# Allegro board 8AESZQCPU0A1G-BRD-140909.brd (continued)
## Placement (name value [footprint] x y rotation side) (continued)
R314  *10K 1% 1/16W  [R0402]  120.37 23.34 90 bottom
R315  0ohm 5% 1/4W  [R1206]  47.5 23.22 90 bottom
R316  487 1% 1/10W  [R0603]  51.56 22.35 0 bottom
R317  100ohm 1% 1/16W  [R0402]  134.6 22.33 0 bottom
R318  1K 1% 1/16W  [R0402]  92.96 21.67 270 bottom
R319  *100ohm 1% 1/16W  [R0402]  134.6 21.32 180 bottom
R320  10K 1% 1/16W  [R0402]  52.32 20.95 0 bottom
R321  4.12K 1%  [R0402]  119.38 19.94 0 bottom
R322  1K 1% 1/16W  [R0402]  99.39 19.89 90 bottom
R323  2.87K 1% 1/16W  [R0402]  117.83 18.21 270 bottom
R324  301K 1% 1/16W  [R0402]  69.19 18.13 90 bottom
R325  22.1K 1% 1/16W  [R0402]  67.92 18.13 90 bottom
R326  2.2 ohm 5% 1/16W  [R0402]  98.96 17.76 180 bottom
R327  ***0ohm 5% 1/16W  [R0402]  75.16 17.48 180 bottom
R328  2.2 ohm 5% 1/16W  [R0402]  90.4 17.23 0 bottom
R329  2.2 ohm 5% 1/16W  [R0402]  98.96 16.67 180 bottom
R330  2.2 ohm 5% 1/16W  [R0402]  90.4 16.21 0 bottom
R331  9.76K 1% 1/16W  [R0402]  69.16 15.95 0 bottom
R332  100K 1% 1/16W  [R0402]  73.66 15.88 0 bottom
R333  2.87K 1% 1/16W  [R0402]  122.22 15.57 270 bottom
R334  3.57K 1% 1/16W  [R0402]  121.11 15.57 270 bottom
R335  301K 1% 1/16W  [R0402]  70.74 15.49 90 bottom
R336  10K 1% 1/16W  [R0402]  52.53 13.54 90 bottom
R337  10K 1% 1/16W  [R0402]  125.48 13.21 90 bottom
R338  10K 1% 1/16W  [R0402]  54.18 12.95 270 bottom
R339  121K 1% 1/16W  [R0402]  47.68 12.5 180 bottom
R340  510 5% 1/16W  [R0402]  58.24 12.22 270 bottom
R341  1K 1% 1/16W  [R0402]  122.28 11.79 180 bottom
R342  10K 1% 1/16W  [R0402]  109.22 11.18 0 bottom
R343  10K 1% 1/16W  [R0402]  122.17 10.41 180 bottom
R344  22.1K 1% 1/16W  [R0402]  47.68 10.31 180 bottom
R345  1K 1% 1/16W  [R0402]  58.24 10.24 270 bottom
R346  1K 1% 1/16W  [R0402]  112.85 10.21 0 bottom
R347  7.68K 1% 1/16W  [R0402]  114.38 8.97 90 bottom
R348  150 1% 1/16W  [R0402]  112.8 8.97 0 bottom
R349  7.68K 1% 1/16W  [R0402]  111.35 8.84 270 bottom
R350  10K 1% 1/16W  [R0402]  93.85 8.76 90 bottom
R351  10K 1% 1/16W  [R0402]  92.58 8.76 90 bottom
R352  6.65K 1% 1/10W  [R0603]  112.55 6.98 90 bottom
R353  20 1% 1/16W  [R0402]  114.15 6.09 90 bottom
R354  *10K 1% 1/16W  [R0402]  109.45 5.1 0 bottom
R355  6.65K 1% 1/10W  [R0603]  113.01 4.39 180 bottom
R356  10K 1% 1/16W  [R0402]  109.45 4.08 0 bottom
R751  ***0ohm 5% 1/16W  [R0402]  66.42 9.14 270 bottom
R752  ***0ohm 5% 1/16W  [R0402]  65.02 9.14 270 bottom
S1  PCIEX16_GOLDFINGER  [PCI_E_X16_A]  98.4 3.5 180 bottom
TP1  TP  [T30]  91.47 63.63 0 top
TP2  TP  [T30]  92.1 62.51 0 top
TP3  TP  [T30]  105.92 52.66 0 top
TP4  TP  [T30]  10.31 40.94 270 top
TP5  TP  [T30]  101.57 37.97 0 top
TP6  TP  [T30]  110.96 35.72 0 top
TP7  TP  [T30]  122.44 56.5 270 bottom
TP8  TP  [T30]  46.25 53.9 180 bottom
TP9  TP  [T30]  124.33 51.54 270 bottom
TP10  TP  [T30]  130.81 40.23 270 bottom
TP11  TP  [T30]  98.17 37.08 180 bottom
TP12  TP  [T30]  120.14 36.96 180 bottom
TP13  TP  [T30]  99.57 36.7 180 bottom
TP14  TP  [T30]  115.87 35.66 180 bottom
TP15  TP  [T30]  122.84 33.69 180 bottom
TP16  TP  [T30]  122.16 30.89 180 bottom
TP17  TP  [T30]  121.34 27.3 180 bottom
TP18  TP  [T30]  124.46 24.33 180 bottom
TP19  TP  [T30]  121.51 24.13 180 bottom
TP20  TP  [T30]  125.53 23.62 180 bottom
TP47  TP  [T30]  43.36 52.28 180 bottom
TP48  TP  [T30]  42.73 61.17 180 bottom
TP49  TP  [T30]  24.36 54.02 180 bottom
TP51  TP  [T30]  41.41 55.16 180 bottom
TP52  TP  [T30]  40.92 63.09 180 bottom
U1  SN74LVC1G07DBVR  [SOT_25]  45.7 70.3 0 top
U2  IR3553MTRPBF  [LCC25_4X6_0P5]  101.06 68.31 90 top
U3  IR3570AMTRPBF  [LCC40_5X5_0P4]  85.81 66.6 270 top
U4  SECOS BAT54C  [SOT_23]  14.73 60.07 180 top
U5  G751-2P1f  [SOP8_1P27_6]  19.43 59.69 0 top
U6  74AVC1T45  [SOT_363]  49.76 57.53 0 top
U7  MAX V 5M1270ZF256  [BGA256_16X16_1P0]  37.32 57.12 90 top
U8  PCA9511ADP  [SOP8_0P65_4P9]  24.26 51.82 0 top
U9  AT24C128C-SSHM-T  [SOP8_1P27_6]  19.43 51.69 0 top
U10  74AVC1T45  [SOT_363]  102.49 50.79 0 top
U11  SN74LVC1G07DBVR  [SOT_25]  39.35 43.91 0 top
U12  IR3553MTRPBF  [LCC25_4X6_0P5]  65.18 42.9 90 top
U13  SN74LVC1G07DBVR  [SOT_25]  39.4 39.29 180 top
U14  AVOTON_EXT_BGA  [BGA1283A]  129.97 39.05 0 top
U15  N25Q128A13ESE40 NEW  [SOP8_1P27_7P9]  28.93 38.59 180 top
U16  W25Q64FVSSIG  [SOP8_1P27_7P9]  34.77 38.59 180 top
U17  HPA01110DQPR  [LCC22_5X6_0P5_JNPR_1]  15.24 38.05 0 top
U18  IRFHS8242TRPBF  [LCC6_2X2_0P65_D]  70.51 34.92 270 top
U19  IRFHS8242TRPBF  [LCC6_2X2_0P65_D]  70.51 32.64 270 top
U20  IR3537MTRPBF  [LCC10_3X3_0P5]  65.94 32.46 270 top
U21  6V61036NDG  [LCC40_5X5_0P4]  98.12 32.16 180 top
U22  BAT54C  [SOT_23]  34.92 32.11 90 top
U23  IR3570AMTRPBF  [LCC40_5X5_0P4]  53.52 31.33 90 top
U24  CAT25256YI-GT3  [SOP8_0P65_6P4]  105.87 28.85 0 top
U25  TPS54225PWPR  [SOP14_0P65_6P4_EP_JNPR_1]  70.59 23.69 0 top
U26  TPS74701DRC  [LCC10_3X3_0P5]  121.18 19 90 top
U27  6U49420D  [LCC48_6X6_0P4]  95.86 18.6 270 top
U28  TPS74701DRC  [LCC10_3X3_0P5]  80.17 17.57 180 top
U29  TPS54225PWPR  [SOP14_0P65_6P4_EP]  50.42 16.36 0 top
U30  TPS74701DRC  [LCC10_3X3_0P5]  121.78 13.35 0 top
U31  IR3899MTRPBF  [LCC17_4X5_0P5]  113.8 8.35 270 top
U32  ISL90728  [SOT_363]  142.82 4.11 180 top
U33  LM321MF/NOPB  [SOT_25]  148.72 3.43 270 top
U34  ISL90727WIE627Z-T7A  [SOT_363]  161.16 3.43 180 top
U35  LM321MF/NOPB  [SOT_25]  167 3.43 270 top
U36  SN74LVC1G07DBVR  [SOT_25]  132.61 68.12 180 bottom
U37  SN74LVC1G07DBVR  [SOT_25]  137.41 67.82 180 bottom
U38  TPS51200DRCR  [LCC10_3X3_0P5]  126.69 66.95 270 bottom
U39  N-CH AP2302GN-HF  [SOT_23]  71.73 18.46 270 bottom
U40  N-CH AP2302GN-HF  [SOT_23]  72.69 13.13 270 bottom
U41  FET N-CH IRLML2402  [SOT_23]  51.46 10.9 270 bottom
U42  FET N-CH IRLML2402  [SOT_23]  55.7 10.64 270 bottom
X1  25MHz 3.3V  [OSC4_SCO_A571]  50.57 63.93 180 top
X2  32.768KHZ  [XTAL2_TXC_9H]  108.48 38.89 90 top
X3  14.31818MHz  [XTAL4_FL2000006]  89.45 23.49 90 top

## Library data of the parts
A1 = SCREW HOLE_3: Tolerance: ***; User Part Number: ***
B1 B3 = 2B: Tolerance: ***; User Part Number: ***
B2 = 2B: User Part Number: ***; Tolerance: ***
C1-C5 C7-C12 C14 C15 C17-C21 C23 C24 C26-C28 C30 C38 C39 C42 C45-C47 C49-C51 C53-C58 C60-C92 C94-C102 C108 C110 C113 C116-C145 C147-C155 C157 C158 C162-C164 C166-C177 C179-C183 C185-C195 C197-C231 C233 C234 C236-C239 C241 C244-C249 C251 C252 C255-C258 C260 C261 C263 C265-C291 C293 C295-C326 C328-C355 C357-C363 C365-C373 C375-C377 C379-C413 C415-C420 C422-C424 C426 C427 C432-C438 C440 C441 C443-C445 C449 C452-C456 C458-C485 C489-C496 C500 C501 = CAP_NP: Tolerance: ***; User Part Number: ***
C6 C16 C25 C48 C52 C59 C93 C107 C111 C146 C156 C159 C160 C165 C178 C184 C232 C262 C292 C294 C356 C364 C374 C378 C414 C439 C446 C451 C457 C486-C488 C497-C499 = CAP_NP: User Part Number: ***; Tolerance: ***
C13 C327 C442 = CAP_NP: Tolerance: ***; User Part Number: ***; room: PHY
C22 C43 C44 C105 C161 C259 = CAP: Tolerance: ***; User Part Number: ***
C29 C31-C35 C37 C40 C41 C235 C240 C242 C243 C253 C254 C428-C431 = CAP_NP: Tolerance: ***; User Part Number: ***; signal model: CAP_NP_C0402_0.1UF_16V_0.1uF_16V
C36 = CAP_NP: Tolerance: ***; User Part Number: ***; signal model: CAP_NP_C0402_0.1UF_16V
C103 C421 C450 = CAP NP: Tolerance: ***; User Part Number: ***; room: REG_1_2V1
C104 C106 C109 C112 = CAP_NP: Tolerance: ***; User Part Number: ***; signal model: CAP_NP_C0402_10NF_50V_10NF_50V
C114 C115 C196 = CAP: User Part Number: ***; Tolerance: ***
C250 C264 C425 R1-R7 R9-R14 R18 R20-R25 R27 R28 R30-R58 R60-R86 R88-R109 R111-R208 R210-R213 R215-R239 R241 R243-R245 R247-R341 R343-R346 R350 R351 R751 R752 = R: Tolerance: ***; User Part Number: ***
D1-D10 = LED: Tolerance: ***; User Part Number: ***
D11 = DIODE_ZENER_0: Tolerance: ***; User Part Number: ***
J1-J5 = JP3_0603: Tolerance: ***; User Part Number: ***
JP1 = JP3: User Part Number: ***; Tolerance: ***
JP2 = JP5A: User Part Number: ***; Tolerance: ***
JP3 JP5 = JTAG_2x5: User Part Number: ***; Tolerance: ***
JP4 = Heatsink_Hole: Tolerance: ***; User Part Number: ***
L1 L2 L4-L6 L8-L10 L14 L17-L21 = INDUCTOR: Tolerance: ***; User Part Number: ***
L3 L7 L11-L13 L15 L16 = INDUCTOR: User Part Number: ***; Tolerance: ***
N1 N3 N5-N9 N12 N14 N18-N20 N27 N28 N31-N34 N37 N38 N40-N42 N51 N56-N58 N60 = R_0OHM: Tolerance: ***; User Part Number: ***
N2 N4 N10 N11 N13 N15-N17 N21-N26 N29 N30 N35 N36 N39 N43-N50 N52-N55 N59 = R_0OHM: User Part Number: ***; Tolerance: ***
P1 = DDR3 ECC SO-DIMM 204PIN: Tolerance: ***; User Part Number: ***; room: DDR3
P2 = CON60,ITP-XDP_0: User Part Number: C21100-002; Tolerance: ***
P3 = SATA CONN_1: Tolerance: ***; User Part Number: ***
P4 = DDR3 ECC SO-DIMM 204PIN: User Part Number: ***; Tolerance: ***; room: DDR3
Q1 Q2 = RT9164_1: Tolerance: ***; User Part Number: ***
R8 R16 R19 R242 R246 R342 R347-R349 R352-R356 = R: User Part Number: ***; Tolerance: ***
R15 R17 R59 R110 R240 = RT: Tolerance: ***; User Part Number: ***
R26 R29 R209 R214 = R: Tolerance: ***; User Part Number: ***; signal model: CAP_NP_C0402_0.1UF_16V_0.1uF_16V
R87 = R: Tolerance: ***; User Part Number: ***; room: MPC8245
S1 = 2134415-2_3: User Part Number: ***; Tolerance: ***
TP1-TP6 TP8 TP11-TP20 TP47-TP49 TP51 TP52 = JP1_0: Tolerance: ***; User Part Number: ***; room: DDR_DIV
TP7 TP9 TP10 = JP1_0: User Part Number: ***; Tolerance: ***; room: DDR_DIV
U1 U11 U13 U36 U37 = SN74LVC1G07DBVR_0: Tolerance: ***; User Part Number: ***
U2 U12 = IR3553MTRPBF: Tolerance: ***; User Part Number: ***
U3 U23 = IR3570AMTRPBF: User Part Number: ***; Tolerance: ***
U4 U22 = RB425DT146: Tolerance: ***; User Part Number: ***
U5 = G751: User Part Number: ***; Tolerance: ***
U6 U10 = 74AVC1T45GW_1: Tolerance: ***; User Part Number: ***
U7 = MAXV5M1270ZF256: Tolerance: ***; User Part Number: ***
U8 = PCA9511ADP: Tolerance: ***; User Part Number: ***
U9 = 24LC08B: User Part Number: ***; Tolerance: ***
U14 = AVOTON_EXT_BGA_0: Tolerance: ***; User Part Number: ***
U15 U16 = W25Q64FVSSIG_0: Tolerance: ***; User Part Number: ***
U17 = TPS53353_1: Tolerance: ***; User Part Number: ***
U18 U19 = IRFHS8242TR2PBF_4: User Part Number: ***; Tolerance: ***
U20 = IR3537MTRPBF: Tolerance: ***; User Part Number: ***
U21 = 6V61036NDG: Tolerance: ***; User Part Number: ***
U24 = 25LC256: Tolerance: ***; User Part Number: ***
U25 U29 = TPS54226_1: Tolerance: ***; User Part Number: ***
U26 U30 = TPS74701DRC: Tolerance: ***; User Part Number: ***
U27 = 6P49420NDG: User Part Number: ***; Tolerance: ***
U28 = TPS74701DRC: User Part Number: ***; Tolerance: ***
U31 = IR3899MTRPBF: User Part Number: ***; Tolerance: ***
U32 = ISL90728: Tolerance: ***; User Part Number: ***
U33 U35 = LM321MF/NOPB: Tolerance: ***; User Part Number: ***
U34 = ISL90728WIE627Z_0: Tolerance: ***; User Part Number: ***
U38 = TPS51200DRCR: Tolerance: ***; User Part Number: ***
U39-U42 = ZVN3310F: Tolerance: ***; User Part Number: ***
X1 = OSC_SMD: User Part Number: ***; Tolerance: ***
X2 = XTAL_0: Tolerance: ***; User Part Number: ***
X3 = XTAL4_3: Tolerance: ***; User Part Number: ***

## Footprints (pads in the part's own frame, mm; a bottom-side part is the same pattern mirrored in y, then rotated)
0_OHM_2PIN
  custom 0.127x0.127 smd: 1(-0.318,0) 2(0.318,0)
2B
  round 1.016 smd: 1(0,0) 2(0,0)
A126_DG_3
  round 3.2 hole 3.2 unplated: (0,0)
  round 1.194 hole 0.381: 3(-1.732,1.732) 4(-1.732,-1.732) 6(0,2.451) 7(0,-2.451) 8(-2.451,0)
BGA256_16X16_1P0
  round 0.457 smd: A1(-7.5,-7.5) A2(-7.5,-6.5) A3(-7.5,-5.5) A4(-7.5,-4.5) A5(-7.5,-3.5) A6(-7.5,-2.5) A7(-7.5,-1.5) A8(-7.5,-0.5) A9(-7.5,0.5) A10(-7.5,1.5) A11(-7.5,2.5) A12(-7.5,3.5) A13(-7.5,4.5) A14(-7.5,5.5) A15(-7.5,6.5) A16(-7.5,7.5) B1(-6.5,-7.5) B2(-6.5,-6.5) B3(-6.5,-5.5) B4(-6.5,-4.5) B5(-6.5,-3.5) B6(-6.5,-2.5) B7(-6.5,-1.5) B8(-6.5,-0.5) B9(-6.5,0.5) B10(-6.5,1.5) B11(-6.5,2.5) B12(-6.5,3.5) B13(-6.5,4.5) B14(-6.5,5.5) B15(-6.5,6.5) B16(-6.5,7.5) C1(-5.5,-7.5) C2(-5.5,-6.5) C3(-5.5,-5.5) C4(-5.5,-4.5) C5(-5.5,-3.5) C6(-5.5,-2.5) C7(-5.5,-1.5) C8(-5.5,-0.5) C9(-5.5,0.5) C10(-5.5,1.5) C11(-5.5,2.5) C12(-5.5,3.5) C13(-5.5,4.5) C14(-5.5,5.5) C15(-5.5,6.5) C16(-5.5,7.5) D1(-4.5,-7.5) D2(-4.5,-6.5) D3(-4.5,-5.5) D4(-4.5,-4.5) D5(-4.5,-3.5) D6(-4.5,-2.5) D7(-4.5,-1.5) D8(-4.5,-0.5) D9(-4.5,0.5) D10(-4.5,1.5) D11(-4.5,2.5) D12(-4.5,3.5) D13(-4.5,4.5) D14(-4.5,5.5) D15(-4.5,6.5) D16(-4.5,7.5) E1(-3.5,-7.5) E2(-3.5,-6.5) E3(-3.5,-5.5) E4(-3.5,-4.5) E5(-3.5,-3.5) E6(-3.5,-2.5) E7(-3.5,-1.5) E8(-3.5,-0.5) E9(-3.5,0.5) E10(-3.5,1.5) E11(-3.5,2.5) E12(-3.5,3.5) E13(-3.5,4.5) E14(-3.5,5.5) E15(-3.5,6.5) E16(-3.5,7.5) F1(-2.5,-7.5) F2(-2.5,-6.5) F3(-2.5,-5.5) F4(-2.5,-4.5) F5(-2.5,-3.5) F6(-2.5,-2.5) F7(-2.5,-1.5) F8(-2.5,-0.5) F9(-2.5,0.5) F10(-2.5,1.5) F11(-2.5,2.5) F12(-2.5,3.5) F13(-2.5,4.5) F14(-2.5,5.5) F15(-2.5,6.5) F16(-2.5,7.5) G1(-1.5,-7.5) G2(-1.5,-6.5) G3(-1.5,-5.5) G4(-1.5,-4.5) G5(-1.5,-3.5) G6(-1.5,-2.5) G7(-1.5,-1.5) G8(-1.5,-0.5) G9(-1.5,0.5) G10(-1.5,1.5) G11(-1.5,2.5) G12(-1.5,3.5) G13(-1.5,4.5) G14(-1.5,5.5) G15(-1.5,6.5) G16(-1.5,7.5) H1(-0.5,-7.5) H2(-0.5,-6.5) H3(-0.5,-5.5) H4(-0.5,-4.5) H5(-0.5,-3.5) H6(-0.5,-2.5) H7(-0.5,-1.5) H8(-0.5,-0.5) H9(-0.5,0.5) H10(-0.5,1.5) H11(-0.5,2.5) H12(-0.5,3.5) H13(-0.5,4.5) H14(-0.5,5.5) H15(-0.5,6.5) H16(-0.5,7.5) J1(0.5,-7.5) J2(0.5,-6.5) J3(0.5,-5.5) J4(0.5,-4.5) J5(0.5,-3.5) J6(0.5,-2.5) J7(0.5,-1.5) J8(0.5,-0.5) J9(0.5,0.5) J10(0.5,1.5) J11(0.5,2.5) J12(0.5,3.5) J13(0.5,4.5) J14(0.5,5.5) J15(0.5,6.5) J16(0.5,7.5) K1(1.5,-7.5) K2(1.5,-6.5) K3(1.5,-5.5) K4(1.5,-4.5) K5(1.5,-3.5) K6(1.5,-2.5) K7(1.5,-1.5) K8(1.5,-0.5) K9(1.5,0.5) K10(1.5,1.5) K11(1.5,2.5) K12(1.5,3.5) K13(1.5,4.5) K14(1.5,5.5) K15(1.5,6.5) K16(1.5,7.5) L1(2.5,-7.5) L2(2.5,-6.5) L3(2.5,-5.5) L4(2.5,-4.5) L5(2.5,-3.5) L6(2.5,-2.5) L7(2.5,-1.5) L8(2.5,-0.5) L9(2.5,0.5) L10(2.5,1.5) L11(2.5,2.5) L12(2.5,3.5) L13(2.5,4.5) L14(2.5,5.5) L15(2.5,6.5) L16(2.5,7.5) M1(3.5,-7.5) M2(3.5,-6.5) M3(3.5,-5.5) M4(3.5,-4.5) M5(3.5,-3.5) M6(3.5,-2.5) M7(3.5,-1.5) M8(3.5,-0.5) M9(3.5,0.5) M10(3.5,1.5) M11(3.5,2.5) M12(3.5,3.5) M13(3.5,4.5) M14(3.5,5.5) M15(3.5,6.5) M16(3.5,7.5) N1(4.5,-7.5) N2(4.5,-6.5) N3(4.5,-5.5) N4(4.5,-4.5) N5(4.5,-3.5) N6(4.5,-2.5) N7(4.5,-1.5) N8(4.5,-0.5) N9(4.5,0.5) N10(4.5,1.5) N11(4.5,2.5) N12(4.5,3.5) N13(4.5,4.5) N14(4.5,5.5) N15(4.5,6.5) N16(4.5,7.5) P1(5.5,-7.5) P2(5.5,-6.5) P3(5.5,-5.5) P4(5.5,-4.5) P5(5.5,-3.5) P6(5.5,-2.5) P7(5.5,-1.5) P8(5.5,-0.5) P9(5.5,0.5) P10(5.5,1.5) P11(5.5,2.5) P12(5.5,3.5) P13(5.5,4.5) P14(5.5,5.5) P15(5.5,6.5) P16(5.5,7.5) R1(6.5,-7.5) R2(6.5,-6.5) R3(6.5,-5.5) R4(6.5,-4.5) R5(6.5,-3.5) R6(6.5,-2.5) R7(6.5,-1.5) R8(6.5,-0.5) R9(6.5,0.5) R10(6.5,1.5) R11(6.5,2.5) R12(6.5,3.5) R13(6.5,4.5) R14(6.5,5.5) R15(6.5,6.5) R16(6.5,7.5) T1(7.5,-7.5) T2(7.5,-6.5) T3(7.5,-5.5) T4(7.5,-4.5) T5(7.5,-3.5) T6(7.5,-2.5) T7(7.5,-1.5) T8(7.5,-0.5) T9(7.5,0.5) T10(7.5,1.5) T11(7.5,2.5) T12(7.5,3.5) T13(7.5,4.5) T14(7.5,5.5) T15(7.5,6.5) T16(7.5,7.5)
BGA1283A
  round 0.406 smd: A5(14.485,-13.111) A6(13.673,-13.111) A8(12.86,-13.111) A59(-12.86,-13.111) A61(-13.673,-13.111) A62(-14.485,-13.111) A64(-15.298,-13.111) A66(-16.111,-13.111) BG1(16.111,9.86) BG66(-16.111,9.86) BJ1(16.111,10.673) BJ66(-16.111,10.673) BK1(16.111,11.485) BK3(15.298,11.485) BK5(14.485,11.485) BK62(-14.485,11.485) BK64(-15.298,11.485) BK66(-16.111,11.485) BM1(16.111,12.298) BM3(15.298,12.298) BM5(14.485,12.298) BM62(-14.485,12.298) BM64(-15.298,12.298) BM66(-16.111,12.298) BP1(16.111,13.111) BP3(15.298,13.111) BP5(14.485,13.111) BP6(13.673,13.111) BP8(12.86,13.111) BP59(-12.86,13.111) BP61(-13.673,13.111) BP62(-14.485,13.111) BP64(-15.298,13.111) BP66(-16.111,13.111) C3(15.298,-12.298) C5(14.485,-12.298) C62(-14.485,-12.298) C64(-15.298,-12.298) C66(-16.111,-12.298) E1(16.111,-11.485) E3(15.298,-11.485) E5(14.485,-11.485) E62(-14.485,-11.485) E64(-15.298,-11.485) E66(-16.111,-11.485) F1(16.111,-10.673) F66(-16.111,-10.673) H1(16.111,-9.86) H66(-16.111,-9.86)
  oval 0.254x0.343 smd: A9(12.173,-13.249) A12(10.548,-13.249) A15(9.109,-13.249) A18(7.671,-13.249) A21(6.045,-13.249) A24(4.606,-13.249) A27(3.168,-13.249) A30(1.542,-13.249) A33(0.103,-13.249) A36(-1.335,-13.249) A39(-2.961,-13.249) A42(-4.4,-13.249) A45(-5.838,-13.249) A48(-7.464,-13.249) A51(-8.902,-13.249) A54(-10.341,-13.249) A57(-11.967,-13.249) BP10(11.967,13.249) BP13(10.341,13.249) BP16(8.902,13.249) BP19(7.464,13.249) BP22(5.838,13.249) BP25(4.4,13.249) BP28(2.961,13.249) BP31(1.335,13.249) BP34(-0.103,13.249) BP37(-1.542,13.249) BP40(-3.168,13.249) BP43(-4.606,13.249) BP46(-6.045,13.249) BP49(-7.671,13.249) BP52(-9.109,13.249) BP55(-10.548,13.249) BP58(-12.173,13.249)
  round 0.305 smd: AA3(15.247,-3.216) AA5(14.014,-3.186) AA47(-6.842,-3.156) AA62(-14.08,-3.388) AA64(-15.243,-3.398) AB2(15.641,-2.611) AB4(14.901,-2.605) AB5(14.204,-2.508) AB20(6.842,-2.916) AB62(-14.204,-2.695) AB63(-14.901,-2.787) AB65(-15.639,-2.818) AC8(12.963,-2.216) AC9(12.201,-2.216) AC11(11.439,-2.216) AC12(10.677,-2.216) AC14(9.915,-2.216) AC15(9.153,-2.216) AC17(8.391,-2.216) AC18(7.629,-2.216) AC20(6.929,-2.216) AC47(-6.929,-2.456) AC49(-7.629,-2.456) AC50(-8.391,-2.456) AC52(-9.153,-2.456) AC53(-9.915,-2.456) AC55(-10.677,-2.456) AC56(-11.439,-2.456) AC58(-12.201,-2.456) AC59(-12.963,-2.456) AD2(15.639,-1.685) AD4(14.901,-1.716) AD5(14.204,-1.808) AD8(12.963,-1.516) AD9(12.201,-1.516) AD11(11.439,-1.516) AD12(10.677,-1.516) AD14(9.915,-1.516) AD15(9.153,-1.516) AD17(8.391,-1.516) AD18(7.629,-1.516) AD20(6.929,-1.516) AD47(-6.929,-1.756) AD49(-7.629,-1.756) AD50(-8.391,-1.756) AD52(-9.153,-1.756) AD53(-9.915,-1.756) AD55(-10.677,-1.756) AD56(-11.439,-1.756) AD58(-12.201,-1.756) AD59(-12.963,-1.756) AD62(-14.204,-1.995) AD63(-14.901,-1.898) AD65(-15.641,-1.892) AE3(15.243,-1.105) AE5(14.08,-1.115) AE47(-6.842,-1.056) AE62(-14.014,-1.317) AE64(-15.247,-1.287) AF2(15.752,-0.618) AF4(14.795,-0.565) AF20(6.842,-0.816) AF62(-14.063,-0.614) AF63(-14.752,-0.783) AF65(-15.806,-0.863) AG5(14.063,-0.407) AG7(13.344,-0.23) AG8(12.582,-0.23) AG10(11.82,-0.23) AG11(11.058,-0.23) AG13(10.296,-0.23) AG14(9.534,-0.23) AG16(8.772,-0.23) AG17(8.01,-0.23) AG19(7.248,-0.23) AG48(-7.248,-0.47) AG50(-8.01,-0.47) AG51(-8.772,-0.47) AG53(-9.534,-0.47) AG54(-10.296,-0.47) AG56(-11.058,-0.47) AG57(-11.82,-0.47) AG59(-12.582,-0.47) AG60(-13.344,-0.47) AG63(-14.543,-0.104) AG64(-15.305,-0.053) AH3(15.305,0.053) AH4(14.543,0.104) AH7(13.344,0.47) AH8(12.582,0.47) AH10(11.82,0.47) AH11(11.058,0.47) AH13(10.296,0.47) AH14(9.534,0.47) AH16(8.772,0.47) AH17(8.01,0.47) AH19(7.248,0.47) AH48(-7.248,0.23) AH50(-8.01,0.23) AH51(-8.772,0.23) AH53(-9.534,0.23) AH54(-10.296,0.23) AH56(-11.058,0.23) AH57(-11.82,0.23) AH59(-12.582,0.23) AH60(-13.344,0.23) AH62(-14.063,0.407) AJ2(15.806,0.863) AJ4(14.752,0.783) AJ5(14.063,0.614) AJ47(-6.842,0.816) AJ63(-14.795,0.565) AJ65(-15.752,0.618) AK3(15.247,1.287) AK5(14.014,1.317) AK20(6.842,1.056) AK62(-14.08,1.115) AK64(-15.243,1.105) AL2(15.641,1.892) AL4(14.901,1.898) AL5(14.204,1.995) AL8(12.963,1.756) AL9(12.201,1.756) AL11(11.439,1.756) AL12(10.677,1.756) AL14(9.915,1.756) AL15(9.153,1.756) AL17(8.391,1.756) AL18(7.629,1.756) AL20(6.929,1.756) AL47(-6.929,1.516) AL49(-7.629,1.516) AL50(-8.391,1.516) AL52(-9.153,1.516) AL53(-9.915,1.516) AL55(-10.677,1.516) AL56(-11.439,1.516) AL58(-12.201,1.516) AL59(-12.963,1.516) AL62(-14.204,1.808) AL63(-14.901,1.716) AL65(-15.639,1.685) AM8(12.963,2.456) AM9(12.201,2.456) AM11(11.439,2.456) AM12(10.677,2.456) AM14(9.915,2.456) AM15(9.153,2.456) AM17(8.391,2.456) AM18(7.629,2.456) AM20(6.929,2.456) AM47(-6.929,2.216) AM49(-7.629,2.216) AM50(-8.391,2.216) AM52(-9.153,2.216) AM53(-9.915,2.216) AM55(-10.677,2.216) AM56(-11.439,2.216) AM58(-12.201,2.216) AM59(-12.963,2.216) AN2(15.639,2.818) AN4(14.901,2.787) AN5(14.204,2.695) AN47(-6.842,2.916) AN62(-14.204,2.508) AN63(-14.901,2.605) AN65(-15.641,2.611) AP3(15.243,3.398) AP5(14.08,3.388) AP20(6.842,3.156) AP62(-14.014,3.186) AP64(-15.247,3.216) AR2(15.752,3.885) AR4(14.795,3.938) AR7(13.344,3.742) AR8(12.582,3.742) AR10(11.82,3.742) AR11(11.058,3.742) AR13(10.296,3.742) AR14(9.534,3.742) AR16(8.772,3.742) AR17(8.01,3.742) AR19(7.248,3.742) AR48(-7.248,3.503) AR50(-8.01,3.503) AR51(-8.772,3.503) AR53(-9.534,3.503) AR54(-10.296,3.503) AR56(-11.058,3.503) AR57(-11.82,3.503) AR59(-12.582,3.503) AR60(-13.344,3.503) AR62(-14.063,3.888) AR63(-14.752,3.72) AR65(-15.806,3.64) AT5(14.063,4.096) AT7(13.344,4.442) AT8(12.582,4.442) AT10(11.82,4.442) AT11(11.058,4.442) AT13(10.296,4.442) AT14(9.534,4.442) AT16(8.772,4.442) AT17(8.01,4.442) AT19(7.248,4.442) AT48(-7.248,4.203) AT50(-8.01,4.203) AT51(-8.772,4.203) AT53(-9.534,4.203) AT54(-10.296,4.203) AT56(-11.058,4.203) AT57(-11.82,4.203) AT59(-12.582,4.203) AT60(-13.344,4.203) AT63(-14.543,4.399) AT64(-15.305,4.45) AU3(15.305,4.556) AU4(14.543,4.607) AU47(-6.726,4.801) AU62(-14.063,4.91) AV2(15.806,5.366) AV4(14.752,5.286) AV5(14.063,5.117) AV63(-14.795,5.068) AV65(-15.752,5.121) AW3(15.247,5.789) AW5(14.014,5.82) AW8(12.963,5.729) AW9(12.201,5.729) AW11(11.439,5.729) AW12(10.677,5.729) AW14(9.915,5.729) AW15(9.153,5.729) AW17(8.175,5.772) AW19(7.475,5.772) AW20(6.801,5.501) AW21(5.901,5.501) AW25(4.203,5.772) AW26(3.503,5.772) AW32(0.23,5.772) AW34(-0.47,5.772) AW41(-3.742,5.772) AW42(-4.442,5.772) AW46(-6.001,5.501) AW47(-6.701,5.501) AW49(-7.715,5.772) AW50(-8.415,5.772) AW52(-9.153,5.489) AW53(-9.915,5.489) AW55(-10.677,5.489) AW56(-11.439,5.489) AW58(-12.201,5.489) AW59(-12.963,5.489) AW62(-14.08,5.617) AW64(-15.243,5.608) AY2(15.641,6.395) AY4(14.901,6.401) AY5(14.204,6.498) AY8(12.963,6.429) AY9(12.201,6.429) AY11(11.439,6.429) AY12(10.677,6.429) AY14(9.915,6.429) AY15(9.153,6.429) AY19(7.475,6.534) AY21(6.189,6.153) AY23(5.489,6.153) AY29(2.216,6.153) AY30(1.516,6.153) AY37(-1.756,6.153) AY38(-2.456,6.153) AY45(-5.729,6.153) AY46(-6.429,6.153) AY52(-9.153,6.189) AY53(-9.915,6.189) AY55(-10.677,6.189) AY56(-11.439,6.189) AY58(-12.201,6.189) AY59(-12.963,6.189) AY62(-14.204,6.311) AY63(-14.901,6.219) AY65(-15.639,6.187) B10(11.824,-12.639) B12(10.897,-12.641) B14(9.869,-12.806) B17(8.388,-12.752) B19(7.321,-12.639) B21(6.394,-12.641) B23(5.366,-12.806) B26(3.885,-12.752) B28(2.818,-12.639) B30(1.892,-12.641) B32(0.863,-12.806) B35(-0.618,-12.752) B37(-1.685,-12.639) B39(-2.611,-12.641) B41(-3.64,-12.806) B44(-5.121,-12.752) B46(-6.188,-12.639) B48(-7.114,-12.641) B50(-8.143,-12.806) B53(-9.624,-12.752) B55(-10.691,-12.639) B57(-11.617,-12.641) BA17(8.175,6.534) BA21(6.189,6.915) BA23(5.489,6.915) BA25(4.203,6.534) BA26(3.503,6.534) BA29(2.216,6.915) BA30(1.516,6.915) BA32(0.23,6.534) BA34(-0.47,6.534) BA37(-1.756,6.915) BA38(-2.456,6.915) BA41(-3.742,6.534) BA42(-4.442,6.534) BA45(-5.729,6.915) BA46(-6.429,6.915) BA49(-7.715,6.534) BA50(-8.415,6.534) BB2(15.639,7.321) BB4(14.901,7.29) BB5(14.204,7.198) BB17(8.175,7.296) BB19(7.475,7.296) BB25(4.203,7.296) BB26(3.503,7.296) BB32(0.23,7.296) BB34(-0.47,7.296) BB41(-3.742,7.296) BB42(-4.442,7.296) BB49(-7.715,7.296) BB50(-8.415,7.296) BB53(-9.534,7.475) BB54(-10.296,7.475) BB56(-11.058,7.475) BB57(-11.82,7.475) BB59(-12.582,7.475) BB60(-13.344,7.475) BB62(-14.204,7.011) BB63(-14.901,7.108) BB65(-15.641,7.114) BC3(15.243,7.901) BC5(14.08,7.891) BC7(13.344,7.715) BC8(12.582,7.715) BC10(11.82,7.715) BC11(11.058,7.715) BC13(10.296,7.715) BC15(9.461,7.677) BC21(6.189,7.677) BC23(5.489,7.677) BC29(2.216,7.677) BC30(1.516,7.677) BC37(-1.756,7.677) BC38(-2.456,7.677) BC45(-5.729,7.677) BC46(-6.429,7.677) BC62(-14.014,7.689) BC64(-15.247,7.719) BD2(15.752,8.388) BD4(14.795,8.441) BD7(13.344,8.415) BD8(12.582,8.415) BD10(11.82,8.415) BD13(10.162,8.439) BD15(9.461,8.439) BD17(8.175,8.058) BD19(7.475,8.058) BD21(6.189,8.439) BD23(5.489,8.439) BD25(4.203,8.058) BD26(3.503,8.058) BD29(2.216,8.439) BD30(1.516,8.439) BD32(0.23,8.058) BD34(-0.47,8.058) BD37(-1.756,8.439) BD38(-2.456,8.439) BD41(-3.742,8.058) BD42(-4.442,8.058) BD45(-5.729,8.439) BD46(-6.429,8.439) BD49(-7.715,8.058) BD50(-8.415,8.058) BD53(-9.701,8.439) BD54(-10.401,8.439) BD59(-12.582,8.175) BD60(-13.344,8.175) BD62(-14.063,8.391) BD63(-14.752,8.222) BD65(-15.806,8.143) BE5(14.063,8.599) BE17(8.175,8.82) BE19(7.475,8.82) BE25(4.203,8.82) BE26(3.503,8.82) BE32(0.23,8.82) BE34(-0.47,8.82) BE41(-3.742,8.82) BE42(-4.442,8.82) BE49(-7.715,8.82) BE50(-8.415,8.82) BE57(-11.688,8.82) BE63(-14.543,8.902) BE64(-15.305,8.953) BF3(15.305,9.059) BF4(14.543,9.109) BF13(10.162,9.201) BF15(9.461,9.201) BF21(6.189,9.201) BF23(5.489,9.201) BF29(2.216,9.201) BF30(1.516,9.201) BF37(-1.756,9.201) BF38(-2.456,9.201) BF45(-5.729,9.201) BF46(-6.429,9.201) BF53(-9.701,9.201) BF54(-10.401,9.201) BF62(-14.063,9.413) BG4(14.752,9.789) BG5(14.063,9.62) BG8(12.963,9.701) BG9(12.201,9.701) BG11(11.448,9.582) BG13(10.162,9.963) BG15(9.461,9.963) BG17(8.175,9.582) BG19(7.475,9.582) BG21(6.189,9.963) BG23(5.489,9.963) BG25(4.203,9.582) BG26(3.503,9.582) BG29(2.216,9.963) BG30(1.516,9.963) BG32(0.23,9.582) BG34(-0.47,9.582) BG37(-1.756,9.963) BG38(-2.456,9.963) BG41(-3.742,9.582) BG42(-4.442,9.582) BG45(-5.729,9.963) BG46(-6.429,9.963) BG49(-7.715,9.582) BG50(-8.415,9.582) BG53(-9.701,9.963) BG54(-10.401,9.963) BG57(-11.688,9.582) BG58(-12.388,9.582) BG63(-14.752,9.582) BH3(15.298,10.318) BH5(14.014,10.323) BH8(12.582,10.344) BH11(11.448,10.344) BH17(8.175,10.344) BH19(7.475,10.344) BH25(4.203,10.344) BH26(3.503,10.344) BH32(0.23,10.344) BH34(-0.47,10.344) BH41(-3.742,10.344) BH42(-4.442,10.344) BH49(-7.715,10.344) BH50(-8.415,10.344) BH57(-11.688,10.344) BH58(-12.388,10.344) BH60(-13.344,10.162) BH62(-14.08,10.12) BH64(-15.298,10.11) BJ4(14.901,10.904) BJ62(-14.204,10.814) BJ63(-14.901,10.696) BK6(13.916,11.063) BK8(12.895,11.063) BK9(12.192,11.014) BK10(11.514,11.204) BK12(10.814,11.204) BK13(10.121,11.074) BK15(9.413,11.063) BK17(8.392,11.063) BK18(7.689,11.014) BK19(7.011,11.204) BK21(6.311,11.204) BK22(5.618,11.074) BK24(4.91,11.063) BK26(3.889,11.063) BK27(3.186,11.014) BK28(2.508,11.204) BK30(1.808,11.204) BK31(1.115,11.074) BK32(0.407,11.063) BK35(-0.614,11.063) BK36(-1.316,11.014) BK37(-1.995,11.204) BK39(-2.695,11.204) BK40(-3.388,11.074) BK42(-4.095,11.063) BK44(-5.117,11.063) BK45(-5.819,11.014) BK46(-6.498,11.204) BK48(-7.198,11.204) BK49(-7.891,11.08) BK51(-8.598,11.063) BK53(-9.62,11.063) BK54(-10.322,11.014) BK56(-11,11.204) BK57(-11.701,11.204) BK58(-12.394,11.08) BK60(-13.102,11.063) BL7(13.405,11.543) BL8(12.726,11.752) BL10(11.611,11.901) BL12(10.722,11.901) BL14(9.571,11.795) BL16(8.902,11.543) BL17(8.223,11.752) BL19(7.108,11.901) BL21(6.219,11.901) BL23(5.068,11.795) BL25(4.4,11.543) BL26(3.72,11.752) BL28(2.605,11.901) BL30(1.716,11.901) BL32(0.565,11.795) BL34(-0.103,11.543) BL35(-0.783,11.752) BL37(-1.898,11.901) BL39(-2.787,11.901) BL41(-3.938,11.795) BL43(-4.606,11.543) BL44(-5.286,11.752) BL46(-6.401,11.901) BL48(-7.29,11.901) BL50(-8.441,11.795) BL52(-9.109,11.543) BL53(-9.789,11.752) BL55(-10.903,11.901) BL57(-11.792,11.901) BL59(-12.933,11.752) BL61(-13.612,11.543) BM7(13.405,12.305) BM9(12.222,12.247) BM13(10.111,12.243) BM16(8.953,12.305) BM18(7.72,12.247) BM22(5.608,12.243) BM25(4.45,12.305) BM27(3.217,12.247) BM31(1.105,12.243) BM34(-0.053,12.305) BM36(-1.286,12.247) BM40(-3.398,12.243) BM43(-4.555,12.305) BM45(-5.789,12.247) BM49(-7.901,12.243) BM52(-9.058,12.305) BM54(-10.292,12.247) BM58(-12.404,12.243) BM61(-13.612,12.305) BN10(11.617,12.641) BN12(10.691,12.639) BN14(9.624,12.752) BN17(8.143,12.806) BN19(7.114,12.641) BN21(6.188,12.639) BN23(5.121,12.752) BN26(3.64,12.806) BN28(2.611,12.641) BN30(1.685,12.639) BN32(0.618,12.752) BN35(-0.863,12.806) BN37(-1.892,12.641) BN39(-2.818,12.639) BN41(-3.885,12.752) BN44(-5.366,12.806) BN46(-6.394,12.641) BN48(-7.321,12.639) BN50(-8.388,12.752) BN53(-9.869,12.806) BN55(-10.897,12.641) BN57(-11.824,12.639) C6(13.612,-12.305) C9(12.404,-12.243) C13(10.292,-12.247) C15(9.058,-12.305) C18(7.901,-12.243) C22(5.789,-12.247) C24(4.555,-12.305) C27(3.398,-12.243) C31(1.286,-12.247) C33(0.053,-12.305) C36(-1.105,-12.243) C40(-3.217,-12.247) C42(-4.45,-12.305) C45(-5.608,-12.243) C49(-7.72,-12.247) C51(-8.953,-12.305) C54(-10.111,-12.243) C58(-12.222,-12.247) C60(-13.405,-12.305) D6(13.612,-11.543) D8(12.933,-11.752) D10(11.792,-11.901) D12(10.903,-11.901) D14(9.789,-11.752) D15(9.109,-11.543) D17(8.441,-11.795) D19(7.29,-11.901) D21(6.401,-11.901) D23(5.286,-11.752) D24(4.606,-11.543) D26(3.938,-11.795) D28(2.787,-11.901) D30(1.898,-11.901) D32(0.783,-11.752) D33(0.103,-11.543) D35(-0.565,-11.795) D37(-1.716,-11.901) D39(-2.605,-11.901) D41(-3.72,-11.752) D42(-4.4,-11.543) D44(-5.068,-11.795) D46(-6.219,-11.901) D48(-7.108,-11.901) D50(-8.223,-11.752) D51(-8.902,-11.543) D53(-9.571,-11.795) D55(-10.722,-11.901) D57(-11.611,-11.901) D59(-12.726,-11.752) D60(-13.405,-11.543) E7(13.102,-11.063) E9(12.394,-11.08) E10(11.701,-11.204) E12(11,-11.204) E13(10.322,-11.014) E14(9.62,-11.063) E16(8.598,-11.063) E18(7.891,-11.08) E19(7.198,-11.204) E21(6.498,-11.204) E22(5.819,-11.014) E23(5.117,-11.063) E25(4.095,-11.063) E27(3.388,-11.08) E28(2.695,-11.204) E30(1.995,-11.204) E31(1.316,-11.014) E32(0.614,-11.063) E34(-0.407,-11.063) E36(-1.115,-11.074) E37(-1.808,-11.204) E39(-2.508,-11.204) E40(-3.186,-11.014) E41(-3.889,-11.063) E43(-4.91,-11.063) E45(-5.618,-11.08) E46(-6.311,-11.204) E48(-7.011,-11.204) E49(-7.689,-11.014) E50(-8.392,-11.063) E52(-9.413,-11.063) E54(-10.121,-11.08) E55(-10.814,-11.204) E57(-11.514,-11.204) E58(-12.192,-11.014) E59(-12.895,-11.063) E61(-13.916,-11.063) F4(14.901,-10.696) F5(14.204,-10.814) F63(-14.901,-10.904) G3(15.298,-10.11) G5(14.08,-10.12) G7(13.344,-10.162) G9(12.388,-10.344) G10(11.688,-10.344) G17(8.415,-10.344) G18(7.715,-10.344) G25(4.442,-10.344) G26(3.742,-10.344) G32(0.47,-10.344) G34(-0.23,-10.344) G41(-3.503,-10.344) G42(-4.203,-10.344) G48(-7.475,-10.344) G50(-8.175,-10.344) G56(-11.448,-10.344) G59(-12.582,-10.344) G62(-14.014,-10.323) G64(-15.298,-10.318) H4(14.752,-9.582) H9(12.388,-9.582) H10(11.688,-9.582) H13(10.401,-9.963) H14(9.701,-9.963) H17(8.415,-9.582) H18(7.715,-9.582) H21(6.429,-9.963) H22(5.729,-9.963) H25(4.442,-9.582) H26(3.742,-9.582) H29(2.456,-9.963) H30(1.756,-9.963) H32(0.47,-9.582) H34(-0.23,-9.582) H37(-1.516,-9.963) H38(-2.216,-9.963) H41(-3.503,-9.582) H42(-4.203,-9.582) H44(-5.489,-9.963) H46(-6.189,-9.963) H48(-7.475,-9.582) H50(-8.175,-9.582) H52(-9.461,-9.963) H54(-10.162,-9.963) H56(-11.448,-9.582) H58(-12.201,-9.701) H59(-12.963,-9.701) H62(-14.063,-9.62) H63(-14.752,-9.789) J5(14.063,-9.413) J13(10.401,-9.201) J14(9.701,-9.201) J21(6.429,-9.201) J22(5.729,-9.201) J29(2.456,-9.201) J30(1.756,-9.201) J37(-1.516,-9.201) J38(-2.216,-9.201) J44(-5.489,-9.201) J46(-6.189,-9.201) J52(-9.461,-9.201) J54(-10.162,-9.201) J63(-14.543,-9.109) J64(-15.305,-9.059) K3(15.305,-8.953) K4(14.543,-8.902) K10(11.688,-8.82) K17(8.415,-8.82) K18(7.715,-8.82) K25(4.442,-8.82) K26(3.742,-8.82) K32(0.47,-8.82) K34(-0.23,-8.82) K41(-3.503,-8.82) K42(-4.203,-8.82) K48(-7.475,-8.82) K50(-8.175,-8.82) K62(-14.063,-8.599) L2(15.806,-8.143) L4(14.752,-8.222) L5(14.063,-8.391) L7(13.344,-8.175) L8(12.582,-8.175) L13(10.401,-8.439) L14(9.701,-8.439) L17(8.415,-8.058) L18(7.715,-8.058) L21(6.429,-8.439) L22(5.729,-8.439) L25(4.442,-8.058) L26(3.742,-8.058) L29(2.456,-8.439) L30(1.756,-8.439) L32(0.47,-8.058) L34(-0.23,-8.058) L37(-1.516,-8.439) L38(-2.216,-8.439) L41(-3.503,-8.058) L42(-4.203,-8.058) L44(-5.489,-8.439) L46(-6.189,-8.439) L48(-7.475,-8.058) L50(-8.175,-8.058) L52(-9.461,-8.439) L54(-10.162,-8.439) L57(-11.82,-8.415) L59(-12.582,-8.415) L60(-13.344,-8.415) L63(-14.795,-8.441) L65(-15.752,-8.388) M3(15.247,-7.719) M5(14.014,-7.689) M21(6.429,-7.677) M22(5.729,-7.677) M29(2.456,-7.677) M30(1.756,-7.677) M37(-1.516,-7.677) M38(-2.216,-7.677) M44(-5.489,-7.677) M46(-6.189,-7.677) M52(-9.461,-7.677) M54(-10.296,-7.715) M56(-11.058,-7.715) M57(-11.82,-7.715) M59(-12.582,-7.715) M60(-13.344,-7.715) M62(-14.08,-7.891) M64(-15.243,-7.901) N2(15.641,-7.114) N4(14.901,-7.108) N5(14.204,-7.011) N7(13.344,-7.475) N8(12.582,-7.475) N10(11.82,-7.475) N11(11.058,-7.475) N13(10.296,-7.475) N14(9.534,-7.475) N17(8.415,-7.296) N18(7.715,-7.296) N25(4.442,-7.296) N26(3.742,-7.296) N32(0.47,-7.296) N34(-0.23,-7.296) N41(-3.503,-7.296) N42(-4.203,-7.296) N48(-7.475,-7.296) N50(-8.175,-7.296) N62(-14.204,-7.198) N63(-14.901,-7.29) N65(-15.639,-7.321) P17(8.415,-6.534) P18(7.715,-6.534) P21(6.429,-6.915) P22(5.729,-6.915) P25(4.442,-6.534) P26(3.742,-6.534) P29(2.456,-6.915) P30(1.756,-6.915) P32(0.47,-6.534) P34(-0.23,-6.534) P37(-1.516,-6.915) P38(-2.216,-6.915) P41(-3.503,-6.534) P42(-4.203,-6.534) P44(-5.489,-6.915) P46(-6.189,-6.915) P48(-7.475,-6.534) P50(-8.175,-6.534) R2(15.639,-6.187) R4(14.901,-6.219) R5(14.204,-6.311) R8(12.963,-6.189) R9(12.201,-6.189) R11(11.439,-6.189) R12(10.677,-6.189) R14(9.915,-6.189) R15(9.153,-6.189) R21(6.429,-6.153) R22(5.729,-6.153) R29(2.456,-6.153) R30(1.756,-6.153) R37(-1.516,-6.153) R38(-2.216,-6.153) R44(-5.489,-6.153) R46(-6.189,-6.153) R52(-9.153,-6.429) R53(-9.915,-6.429) R55(-10.677,-6.429) R56(-11.439,-6.429) R58(-12.201,-6.429) R59(-12.963,-6.429) R62(-14.204,-6.498) R63(-14.901,-6.401) R65(-15.641,-6.395) T3(15.243,-5.608) T5(14.08,-5.617) T17(8.415,-5.772) T18(7.715,-5.772) T20(6.701,-5.501) T21(6.001,-5.501) T25(4.442,-5.772) T26(3.742,-5.772) T32(0.47,-5.772) T34(-0.23,-5.772) T41(-3.503,-5.772) T42(-4.203,-5.772) T45(-5.901,-5.501) T47(-6.801,-5.501) T48(-7.475,-5.772) T50(-8.175,-5.772) T52(-9.153,-5.729) T53(-9.915,-5.729) T55(-10.677,-5.729) T56(-11.439,-5.729) T58(-12.201,-5.729) T59(-12.963,-5.729) T62(-14.014,-5.82) T64(-15.247,-5.789) U2(15.752,-5.121) U4(14.795,-5.068) U8(12.963,-5.489) U9(12.201,-5.489) U11(11.439,-5.489) U12(10.677,-5.489) U14(9.915,-5.489) U15(9.153,-5.489) U62(-14.063,-5.117) U63(-14.752,-5.286) U65(-15.806,-5.366) V5(14.063,-4.91) V20(6.726,-4.801) V63(-14.543,-4.607) V64(-15.305,-4.556) W3(15.305,-4.45) W4(14.543,-4.399) W7(13.344,-4.203) W8(12.582,-4.203) W10(11.82,-4.203) W11(11.058,-4.203) W13(10.296,-4.203) W14(9.534,-4.203) W16(8.772,-4.203) W17(8.01,-4.203) W19(7.248,-4.203) W48(-7.248,-4.442) W50(-8.01,-4.442) W51(-8.772,-4.442) W53(-9.534,-4.442) W54(-10.296,-4.442) W56(-11.058,-4.442) W57(-11.82,-4.442) W59(-12.582,-4.442) W60(-13.344,-4.442) W62(-14.063,-4.096) Y2(15.806,-3.64) Y4(14.752,-3.72) Y5(14.063,-3.888) Y7(13.344,-3.503) Y8(12.582,-3.503) Y10(11.82,-3.503) Y11(11.058,-3.503) Y13(10.296,-3.503) Y14(9.534,-3.503) Y16(8.772,-3.503) Y17(8.01,-3.503) Y19(7.248,-3.503) Y48(-7.248,-3.742) Y50(-8.01,-3.742) Y51(-8.772,-3.742) Y53(-9.534,-3.742) Y54(-10.296,-3.742) Y56(-11.058,-3.742) Y57(-11.82,-3.742) Y59(-12.582,-3.742) Y60(-13.344,-3.742) Y63(-14.795,-3.938) Y65(-15.752,-3.885)
  round 0.381 smd: AA21(6.001,-3.2) AA23(5.201,-3.2) AA25(4.401,-3.2) AA26(3.6,-3.2) AA28(2.8,-3.2) AA29(2,-3.2) AA31(1.2,-3.2) AA32(0.4,-3.2) AA34(-0.4,-3.2) AA36(-1.2,-3.2) AA38(-2,-3.2) AA39(-2.8,-3.2) AA41(-3.6,-3.2) AA42(-4.401,-3.2) AA44(-5.201,-3.2) AA46(-6.001,-3.2) AC21(6.001,-2.4) AC23(5.201,-2.4) AC25(4.401,-2.4) AC26(3.6,-2.4) AC28(2.8,-2.4) AC29(2,-2.4) AC31(1.2,-2.4) AC32(0.4,-2.4) AC34(-0.4,-2.4) AC36(-1.2,-2.4) AC38(-2,-2.4) AC39(-2.8,-2.4) AC41(-3.6,-2.4) AC42(-4.401,-2.4) AC44(-5.201,-2.4) AC46(-6.001,-2.4) AD21(6.001,-1.6) AD23(5.201,-1.6) AD25(4.401,-1.6) AD26(3.6,-1.6) AD28(2.8,-1.6) AD29(2,-1.6) AD31(1.2,-1.6) AD32(0.4,-1.6) AD34(-0.4,-1.6) AD36(-1.2,-1.6) AD38(-2,-1.6) AD39(-2.8,-1.6) AD41(-3.6,-1.6) AD42(-4.401,-1.6) AD44(-5.201,-1.6) AD46(-6.001,-1.6) AF21(6.001,-0.8) AF23(5.201,-0.8) AF25(4.401,-0.8) AF26(3.6,-0.8) AF28(2.8,-0.8) AF29(2,-0.8) AF31(1.2,-0.8) AF32(0.4,-0.8) AF34(-0.4,-0.8) AF36(-1.2,-0.8) AF38(-2,-0.8) AF39(-2.8,-0.8) AF41(-3.6,-0.8) AF42(-4.401,-0.8) AF44(-5.201,-0.8) AF46(-6.001,-0.8) AG21(6.001,0) AG23(5.201,0) AG25(4.401,0) AG26(3.6,0) AG28(2.8,0) AG29(2,0) AG31(1.2,0) AG32(0.4,0) AG34(-0.4,0) AG36(-1.2,0) AG38(-2,0) AG39(-2.8,0) AG41(-3.6,0) AG42(-4.401,0) AG44(-5.201,0) AG46(-6.001,0) AJ21(6.001,0.8) AJ23(5.201,0.8) AJ25(4.401,0.8) AJ26(3.6,0.8) AJ28(2.8,0.8) AJ29(2,0.8) AJ31(1.2,0.8) AJ32(0.4,0.8) AJ34(-0.4,0.8) AJ36(-1.2,0.8) AJ38(-2,0.8) AJ39(-2.8,0.8) AJ41(-3.6,0.8) AJ42(-4.401,0.8) AJ44(-5.201,0.8) AJ46(-6.001,0.8) AL21(6.001,1.6) AL23(5.201,1.6) AL25(4.401,1.6) AL26(3.6,1.6) AL28(2.8,1.6) AL29(2,1.6) AL31(1.2,1.6) AL32(0.4,1.6) AL34(-0.4,1.6) AL36(-1.2,1.6) AL38(-2,1.6) AL39(-2.8,1.6) AL41(-3.6,1.6) AL42(-4.401,1.6) AL44(-5.201,1.6) AL46(-6.001,1.6) AM21(6.001,2.4) AM23(5.201,2.4) AM25(4.401,2.4) AM26(3.6,2.4) AM28(2.8,2.4) AM29(2,2.4) AM31(1.2,2.4) AM32(0.4,2.4) AM34(-0.4,2.4) AM36(-1.2,2.4) AM38(-2,2.4) AM39(-2.8,2.4) AM41(-3.6,2.4) AM42(-4.401,2.4) AM44(-5.201,2.4) AM46(-6.001,2.4) AP21(6.001,3.2) AP23(5.201,3.2) AP25(4.401,3.2) AP26(3.6,3.2) AP28(2.8,3.2) AP29(2,3.2) AP31(1.2,3.2) AP32(0.4,3.2) AP34(-0.4,3.2) AP36(-1.2,3.2) AP38(-2,3.2) AP39(-2.8,3.2) AP41(-3.6,3.2) AP42(-4.401,3.2) AP44(-5.201,3.2) AP46(-6.001,3.2) AT21(6.001,4) AT23(5.201,4) AT25(4.401,4) AT26(3.6,4) AT28(2.8,4) AT29(2,4) AT31(1.2,4) AT32(0.4,4) AT34(-0.4,4) AT36(-1.2,4) AT38(-2,4) AT39(-2.8,4) AT41(-3.6,4) AT42(-4.401,4) AT44(-5.201,4) AT46(-6.001,4) AU21(6.001,4.801) AU23(5.201,4.801) AU25(4.401,4.801) AU26(3.6,4.801) AU28(2.8,4.801) AU29(2,4.801) AU31(1.2,4.801) AU32(0.4,4.801) AU34(-0.4,4.801) AU36(-1.2,4.801) AU38(-2,4.801) AU39(-2.8,4.801) AU41(-3.6,4.801) AU42(-4.401,4.801) AU44(-5.201,4.801) AU46(-6.001,4.801) AW23(5.201,5.501) AW28(2.8,5.501) AW30(1.9,5.501) AW31(1.2,5.501) AW36(-1.2,5.501) AW38(-2.1,5.501) AW39(-2.8,5.501) AW44(-5.201,5.501) T23(5.201,-5.501) T28(2.8,-5.501) T29(2.1,-5.501) T31(1.2,-5.501) T36(-1.2,-5.501) T37(-1.9,-5.501) T39(-2.8,-5.501) T44(-5.201,-5.501) V21(6.001,-4.801) V23(5.201,-4.801) V25(4.401,-4.801) V26(3.6,-4.801) V28(2.8,-4.801) V29(2,-4.801) V31(1.2,-4.801) V32(0.4,-4.801) V34(-0.4,-4.801) V36(-1.2,-4.801) V38(-2,-4.801) V39(-2.8,-4.801) V41(-3.6,-4.801) V42(-4.401,-4.801) V44(-5.201,-4.801) V46(-6.001,-4.801) W21(6.001,-4) W23(5.201,-4) W25(4.401,-4) W26(3.6,-4) W28(2.8,-4) W29(2,-4) W31(1.2,-4) W32(0.4,-4) W34(-0.4,-4) W36(-1.2,-4) W38(-2,-4) W39(-2.8,-4) W41(-3.6,-4) W42(-4.401,-4) W44(-5.201,-4) W46(-6.001,-4)
  oval 0.343x0.254 smd: AA66(-16.249,-3.168) AB1(16.249,-2.961) AD66(-16.249,-1.542) AE1(16.249,-1.335) AG66(-16.249,-0.104) AH1(16.249,0.104) AK66(-16.249,1.335) AL1(16.249,1.542) AN66(-16.249,2.961) AP1(16.249,3.168) AT66(-16.249,4.399) AU1(16.249,4.607) AW66(-16.249,5.838) AY1(16.249,6.045) BB66(-16.249,7.464) BC1(16.249,7.671) BE66(-16.249,8.902) BF1(16.249,9.109) J66(-16.249,-9.109) K1(16.249,-8.902) M66(-16.249,-7.671) N1(16.249,-7.464) R66(-16.249,-6.045) T1(16.249,-5.838) V66(-16.249,-4.607) W1(16.249,-4.399)
BSH_60_01_A
  round 1.016 hole 1.016 unplated: (-10.063,2.666) (10.063,2.666)
  rect 0.279x2.794 smd: 1(-7.25,-3.239) 2(-7.25,3.239) 3(-6.75,-3.239) 4(-6.75,3.239) 5(-6.25,-3.239) 6(-6.25,3.239) 7(-5.75,-3.239) 8(-5.75,3.239) 9(-5.25,-3.239) 10(-5.25,3.239) 11(-4.75,-3.239) 12(-4.75,3.239) 13(-4.25,-3.239) 14(-4.25,3.239) 15(-3.75,-3.239) 16(-3.75,3.239) 17(-3.25,-3.239) 18(-3.25,3.239) 19(-2.75,-3.239) 20(-2.75,3.239) 21(-2.25,-3.239) 22(-2.25,3.239) 23(-1.75,-3.239) 24(-1.75,3.239) 25(-1.25,-3.239) 26(-1.25,3.239) 27(-0.75,-3.239) 28(-0.75,3.239) 29(-0.25,-3.239) 30(-0.25,3.239) 31(0.25,-3.239) 32(0.25,3.239) 33(0.75,-3.239) 34(0.75,3.239) 35(1.25,-3.239) 36(1.25,3.239) 37(1.75,-3.239) 38(1.75,3.239) 39(2.25,-3.239) 40(2.25,3.239) 41(2.75,-3.239) 42(2.75,3.239) 43(3.25,-3.239) 44(3.25,3.239) 45(3.75,-3.239) 46(3.75,3.239) 47(4.25,-3.239) 48(4.25,3.239) 49(4.75,-3.239) 50(4.75,3.239) 51(5.25,-3.239) 52(5.25,3.239) 53(5.75,-3.239) 54(5.75,3.239) 55(6.25,-3.239) 56(6.25,3.239) 57(6.75,-3.239) 58(6.75,3.239) 59(7.25,-3.239) 60(7.25,3.239)
C0402
  rect 0.508x0.508 smd: 1(-0.445,0) 2(0.445,0)
C0402-HANK
  custom 0.127x0.127 smd: 1(-0.483,0) 2(0.483,0)
C0603
  rect 0.991x0.889 smd: 1(-0.737,0) 2(0.737,0)
C0805
  rect 1.27x1.473 smd: 1(-1.041,0) 2(1.041,0)
C1206
  rect 1.524x1.727 smd: 1(-1.778,0) 2(1.778,0)
C1210
  rect 1.778x2.54 smd: 1(-1.524,0) 2(1.524,0)
C7343
  rect 2.413x2.591 smd: 1(-3.378,0) 2(3.353,0)
HEATSINK_60X72_4P
  round 4.191 hole 3.2: 1(-21,21) 3(21,-17)
  round 2.794 hole 1.803: 2(-21,-17) 4(21,21)
JP2X5_SMD_JNPR_1
  rect 1.27x3.048 smd: 1(-5.08,-2.54) 2(-5.08,2.54) 3(-2.54,-2.54) 4(-2.54,2.54) 5(0,-2.54) 6(0,2.54) 7(2.54,-2.54) 8(2.54,2.54) 9(5.08,-2.54) 10(5.08,2.54)
JP3
  rect 1.651x1.651 hole 1.092: 1(0,0)
  round 1.651 hole 1.092: 2(2.54,0) 3(5.08,0)
JP3_0402
  rect 0.508x0.508 smd: 1(-0.889,0) 2(0,0) 3(0.889,0)
JP5A
  rect 1.651x1.651 hole 1.092: 1(0,0)
  round 1.651 hole 1.092: 3(5.08,0) 4(7.62,0) 5(10.16,0)
KP_1608
  rect 0.889x0.889 smd: 1(-0.864,0) 2(0.864,0)
L2_DO1813HC
  rect 1.778x3.81 smd: 1(-3.556,0) 2(3.556,0)
L2_INTFV0705
  rect 2.286x3.429 smd: 1(-2.997,0) 2(2.997,0)
L2_IUT107
  rect 3.302x2.54 smd: 1(-4.496,0) 2(4.496,0)
L2_MHCC10040
  rect 3.556x3.302 smd: 1(-4.826,0) 2(4.826,0)
L2_SCDS73T
  rect 2.032x2.286 smd: 1(-3.175,0) 2(3.175,0)
L2_XAL7070
  rect 1.651x7.112 smd: 1(-2.285,0) 2(2.285,0)
L0402
  rect 0.508x0.508 smd: 1(-0.445,0) 2(0.445,0)
L0603
  rect 0.991x0.889 smd: 1(-0.737,0) 2(0.737,0)
L0805
  rect 1.27x1.473 smd: 1(-1.041,0) 2(1.041,0)
LCC6_2X2_0P65_D
  rect 0.356x0.508 smd: 1(-0.65,-0.953) 2(0,-0.953) 3(0.65,-0.953) 4(0.65,0.953) 5(0,0.953) 6(-0.65,0.953)
  rect 1.041x1.194 smd: 7(-0.255,0)
  rect 0.229x0.787 smd: 8(0.735,0)
LCC10_3X3_0P5
  rect 0.305x0.914 smd: 1(-1,-1.537) 2(-0.5,-1.537) 3(0,-1.537) 4(0.5,-1.537) 5(1,-1.537) 6(1,1.537) 7(0.5,1.537) 8(0,1.537) 9(-0.5,1.537) 10(-1,1.537)
  custom 0.445x0.445 hole 0.254: 11(0,0)
LCC17_4X5_0P5
  rect 0.254x0.762 smd: 1(-1.5,-2.43) 2(-1,-2.43) 3(-0.5,-2.43) 4(0,-2.43) 5(0.5,-2.43) 6(1,-2.43) 7(1.5,-2.43)
  rect 0.762x0.254 smd: 8(1.925,-1.65) 9(1.925,-1.15) 10(1.925,-0.65) 14(-1.925,-0.65) 15(-1.925,-1.15) 16(-1.925,-1.65)
  custom 0.2x0.2 smd: 11(1.695,1.205)
  custom 0.405x0.405 smd: 12(0.282,1.39)
  custom 0.342x0.342 smd: 13(-1.415,1.205)
  rect 2.21x1.219 smd: 17(0,-1.15)
LCC22_5X6_0P5_JNPR_1
  rect 0.254x0.864 smd: 1(-2.5,-2.482) 2(-2,-2.482) 3(-1.5,-2.482) 4(-1,-2.482) 5(-0.5,-2.482) 6(0,-2.482) 7(0.5,-2.482) 8(1,-2.482) 9(1.5,-2.482) 10(2,-2.482) 11(2.5,-2.482) 12(2.5,2.482) 13(2,2.482) 14(1.5,2.482) 15(1,2.482) 16(0.5,2.482) 17(0,2.482) 18(-0.5,2.482) 19(-1,2.482) 20(-1.5,2.482) 21(-2,2.482) 22(-2.5,2.482)
  rect 6.045x3.353 smd: 23(0,0)
LCC25_4X6_0P5
  oval 0.66x0.254 smd: 1(-1.975,2.275) 2(-1.975,1.775) 3(-1.975,1.275) 4(-1.975,0.775) 5(-1.975,0.275) 6(-1.975,-2.375) 16(1.975,2.425)
  rect 0.254x0.889 smd: 7(-1,-2.863) 8(-0.5,-2.863) 9(0,-2.863) 10(0.5,-2.863) 11(1,-2.863)
  custom 0.362x0.362 smd: 12(1.975,-1.6)
  rect 0.66x0.406 smd: 13(1.975,-0.559) 15(1.975,1.805)
  custom 0.382x0.382 smd: 14(1.975,0.575)
  oval 0.254x0.66 smd: 17(1.425,2.975) 18(0.925,2.975) 19(0.425,2.975) 20(-0.075,2.975) 21(-0.575,2.975) 22(-1.075,2.975) 23(-1.575,2.975)
  rect 1.626x1.956 smd: 24(-0.486,1.325)
  rect 0.559x0.356 smd: 25(-1.056,-0.53)
LCC40_5X5_0P4
  rect 0.203x0.914 smd: 1(-1.8,-2.54) 2(-1.4,-2.54) 3(-1,-2.54) 4(-0.6,-2.54) 5(-0.2,-2.54) 6(0.2,-2.54) 7(0.6,-2.54) 8(1,-2.54) 9(1.4,-2.54) 10(1.8,-2.54) 21(1.8,2.54) 22(1.4,2.54) 23(1,2.54) 24(0.6,2.54) 25(0.2,2.54) 26(-0.2,2.54) 27(-0.6,2.54) 28(-1,2.54) 29(-1.4,2.54) 30(-1.8,2.54)
  rect 0.914x0.203 smd: 11(2.54,-1.8) 12(2.54,-1.4) 13(2.54,-1) 14(2.54,-0.6) 15(2.54,-0.2) 16(2.54,0.2) 17(2.54,0.6) 18(2.54,1) 19(2.54,1.4) 20(2.54,1.8) 31(-2.54,1.8) 32(-2.54,1.4) 33(-2.54,1) 34(-2.54,0.6) 35(-2.54,0.2) 36(-2.54,-0.2) 37(-2.54,-0.6) 38(-2.54,-1) 39(-2.54,-1.4) 40(-2.54,-1.8)
  rect 3.607x3.607 hole 0.254: 41(0,0)
LCC48_6X6_0P4
  rect 0.203x0.889 smd: 1(-2.2,-2.997) 2(-1.8,-2.997) 3(-1.4,-2.997) 4(-1,-2.997) 5(-0.6,-2.997) 6(-0.2,-2.997) 7(0.2,-2.997) 8(0.6,-2.997) 9(1,-2.997) 10(1.4,-2.997) 11(1.8,-2.997) 12(2.2,-2.997) 25(2.2,2.997) 26(1.8,2.997) 27(1.4,2.997) 28(1,2.997) 29(0.6,2.997) 30(0.2,2.997) 31(-0.2,2.997) 32(-0.6,2.997) 33(-1,2.997) 34(-1.4,2.997) 35(-1.8,2.997) 36(-2.2,2.997)
  rect 0.889x0.203 smd: 13(2.997,-2.2) 14(2.997,-1.8) 15(2.997,-1.4) 16(2.997,-1) 17(2.997,-0.6) 18(2.997,-0.2) 19(2.997,0.2) 20(2.997,0.6) 21(2.997,1) 22(2.997,1.4) 23(2.997,1.8) 24(2.997,2.2) 37(-2.997,2.2) 38(-2.997,1.8) 39(-2.997,1.4) 40(-2.997,1) 41(-2.997,0.6) 42(-2.997,0.2) 43(-2.997,-0.2) 44(-2.997,-0.6) 45(-2.997,-1) 46(-2.997,-1.4) 47(-2.997,-1.8) 48(-2.997,-2.2)
  rect 4.572x4.572 hole 0.254: 49(0,0)
LED_KPHHS_1005QB
  rect 0.711x0.508 smd: 1(-0.457,0) 2(0.457,0)
OSC4_SCO_A571
  rect 1.524x1.27 smd: 1(-1.219,-0.991) 2(1.219,-0.991) 3(1.219,0.991) 4(-1.219,0.991)
PCI_E_X16_A
  rect 0.762x3.701 smd: A1(0,0.75)
  rect 0.762x4.699 smd: A2(1,0.25) A3(2,0.25) A4(3,0.25) A5(4,0.25) A6(5,0.25) A7(6,0.25) A8(7,0.25) A9(8,0.25) A10(9,0.25) A11(10,0.25) A12(13.05,0.25) A13(14.05,0.25) A14(15.05,0.25) A15(16.05,0.25) A16(17.05,0.25) A17(18.05,0.25) A18(19.05,0.25) A19(20.05,0.25) A20(21.05,0.25) A21(22.05,0.25) A22(23.05,0.25) A23(24.05,0.25) A24(25.05,0.25) A25(26.05,0.25) A26(27.05,0.25) A27(28.05,0.25) A28(29.05,0.25) A29(30.05,0.25) A30(31.05,0.25) A31(32.05,0.25) A32(33.05,0.25) A33(34.05,0.25) A34(35.05,0.25) A35(36.05,0.25) A36(37.05,0.25) A37(38.05,0.25) A38(39.05,0.25) A39(40.05,0.25) A40(41.05,0.25) A41(42.05,0.25) A42(43.05,0.25) A43(44.05,0.25) A44(45.05,0.25) A45(46.05,0.25) A46(47.05,0.25) A47(48.05,0.25) A48(49.05,0.25) A49(50.05,0.25) A50(51.05,0.25) A51(52.05,0.25) A52(53.05,0.25) A53(54.05,0.25) A54(55.05,0.25) A55(56.05,0.25) A56(57.05,0.25) A57(58.05,0.25) A58(59.05,0.25) A59(60.05,0.25) A60(61.05,0.25) A61(62.05,0.25) A62(63.05,0.25) A63(64.05,0.25) A64(65.05,0.25) A65(66.05,0.25) A66(67.05,0.25) A67(68.05,0.25) A68(69.05,0.25) A69(70.05,0.25) A70(71.05,0.25) A71(72.05,0.25) A72(73.05,0.25) A73(74.05,0.25) A74(75.05,0.25) A75(76.05,0.25) A76(77.05,0.25) A77(78.05,0.25) A78(79.05,0.25) A79(80.05,0.25) A80(81.05,0.25) A81(82.05,0.25) A82(83.05,0.25) B1(0,0.25) B2(1,0.25) B3(2,0.25) B4(3,0.25) B5(4,0.25) B6(5,0.25) B7(6,0.25) B8(7,0.25) B9(8,0.25) B10(9,0.25) B11(10,0.25) B12(13.05,0.25) B13(14.05,0.25) B14(15.05,0.25) B15(16.05,0.25) B16(17.05,0.25) B17(18.05,0.25) B18(19.05,0.25) B19(20.05,0.25) B20(21.05,0.25) B21(22.05,0.25) B22(23.05,0.25) B23(24.05,0.25) B24(25.05,0.25) B25(26.05,0.25) B26(27.05,0.25) B27(28.05,0.25) B28(29.05,0.25) B29(30.05,0.25) B30(31.05,0.25) B31(32.05,0.25) B32(33.05,0.25) B33(34.05,0.25) B34(35.05,0.25) B35(36.05,0.25) B36(37.05,0.25) B37(38.05,0.25) B38(39.05,0.25) B39(40.05,0.25) B40(41.05,0.25) B41(42.05,0.25) B42(43.05,0.25) B43(44.05,0.25) B44(45.05,0.25) B45(46.05,0.25) B46(47.05,0.25) B47(48.05,0.25) B48(49.05,0.25) B49(50.05,0.25) B50(51.05,0.25) B51(52.05,0.25) B52(53.05,0.25) B53(54.05,0.25) B54(55.05,0.25) B55(56.05,0.25) B56(57.05,0.25) B57(58.05,0.25) B58(59.05,0.25) B59(60.05,0.25) B60(61.05,0.25) B61(62.05,0.25) B62(63.05,0.25) B63(64.05,0.25) B64(65.05,0.25) B65(66.05,0.25) B66(67.05,0.25) B67(68.05,0.25) B68(69.05,0.25) B69(70.05,0.25) B70(71.05,0.25) B71(72.05,0.25) B72(73.05,0.25) B73(74.05,0.25) B74(75.05,0.25) B75(76.05,0.25) B76(77.05,0.25) B77(78.05,0.25) B78(79.05,0.25) B79(80.05,0.25) B80(81.05,0.25) B81(82.05,0.25) B82(83.05,0.25)
R0402
  rect 0.508x0.508 smd: 1(-0.445,0) 2(0.445,0)
R0402-HANK
  custom 0.127x0.127 smd: 1(-0.483,0) 2(0.483,0)
R0603
  rect 0.991x0.889 smd: 1(-0.737,0) 2(0.737,0)
R0805
  rect 1.27x1.473 smd: 1(-1.041,0) 2(1.041,0)
R1206
  rect 1.524x1.727 smd: 1(-1.778,0) 2(1.778,0)
SATA2_R_SMD
  round 1.6 hole 1.6 unplated: (0,0) (33.19,0)
  rect 0.889x2.413 smd: 1(32.475,3) 2(31.205,3) 3(29.935,3) 4(28.665,3) 5(27.395,3) 6(26.125,3) 7(24.855,3) 8(18.5,3) 9(17.23,3) 10(15.96,3) 11(14.69,2.5) 12(13.42,3) 13(12.15,3) 14(10.88,3) 15(9.61,3) 16(8.34,3) 17(7.07,3) 18(5.8,3) 19(4.53,2.5) 20(3.26,3) 21(1.99,3) 22(0.72,3)
  oval 1.778x3.302 hole 1.016x2.54: 23(35.305,0.76) 24(-2.115,0.76)
SOD_123
  rect 1.016x0.762 smd: 1(-1.905,0) 2(1.905,0)
SODIMM_204R
  round 1.6 hole 1.6 unplated: (0,0)
  round 1.092 hole 1.092 unplated: (66.8,0)
  rect 0.356x2.032 smd: 1(1.75,-4.1) 2(2.05,4.1) 3(2.35,-4.1) 4(2.65,4.1) 5(2.95,-4.1) 6(3.25,4.1) 7(3.55,-4.1) 8(3.85,4.1) 9(4.15,-4.1) 10(4.45,4.1) 11(4.75,-4.1) 12(5.05,4.1) 13(5.35,-4.1) 14(5.65,4.1) 15(5.95,-4.1) 16(6.25,4.1) 17(6.55,-4.1) 18(6.85,4.1) 19(7.15,-4.1) 20(7.45,4.1) 21(7.75,-4.1) 22(8.05,4.1) 23(8.35,-4.1) 24(8.65,4.1) 25(8.95,-4.1) 26(9.25,4.1) 27(9.55,-4.1) 28(9.85,4.1) 29(10.15,-4.1) 30(10.45,4.1) 31(10.75,-4.1) 32(11.05,4.1) 33(11.35,-4.1) 34(11.65,4.1) 35(11.95,-4.1) 36(12.25,4.1) 37(12.55,-4.1) 38(12.85,4.1) 39(13.15,-4.1) 40(13.45,4.1) 41(13.75,-4.1) 42(14.05,4.1) 43(14.35,-4.1) 44(14.65,4.1) 45(14.95,-4.1) 46(15.25,4.1) 47(15.55,-4.1) 48(15.85,4.1) 49(16.15,-4.1) 50(16.45,4.1) 51(16.75,-4.1) 52(17.05,4.1) 53(17.35,-4.1) 54(17.65,4.1) 55(17.95,-4.1) 56(18.25,4.1) 57(18.55,-4.1) 58(18.85,4.1) 59(19.15,-4.1) 60(19.45,4.1) 61(19.75,-4.1) 62(20.05,4.1) 63(20.35,-4.1) 64(20.65,4.1) 65(20.95,-4.1) 66(21.25,4.1) 67(21.55,-4.1) 68(21.85,4.1) 69(22.15,-4.1) 70(22.45,4.1) 71(22.75,-4.1) 72(23.05,4.1) 73(25.75,-4.1) 74(26.05,4.1) 75(26.35,-4.1) 76(26.65,4.1) 77(26.95,-4.1) 78(27.25,4.1) 79(27.55,-4.1) 80(27.85,4.1) 81(28.15,-4.1) 82(28.45,4.1) 83(28.75,-4.1) 84(29.05,4.1) 85(29.35,-4.1) 86(29.65,4.1) 87(29.95,-4.1) 88(30.25,4.1) 89(30.55,-4.1) 90(30.85,4.1) 91(31.15,-4.1) 92(31.45,4.1) 93(31.75,-4.1) 94(32.05,4.1) 95(32.35,-4.1) 96(32.65,4.1) 97(32.95,-4.1) 98(33.25,4.1) 99(33.55,-4.1) 100(33.85,4.1) 101(34.15,-4.1) 102(34.45,4.1) 103(34.75,-4.1) 104(35.05,4.1) 105(35.35,-4.1) 106(35.65,4.1) 107(35.95,-4.1) 108(36.25,4.1) 109(36.55,-4.1) 110(36.85,4.1) 111(37.15,-4.1) 112(37.45,4.1) 113(37.75,-4.1) 114(38.05,4.1) 115(38.35,-4.1) 116(38.65,4.1) 117(38.95,-4.1) 118(39.25,4.1) 119(39.55,-4.1) 120(39.85,4.1) 121(40.15,-4.1) 122(40.45,4.1) 123(40.75,-4.1) 124(41.05,4.1) 125(41.35,-4.1) 126(41.65,4.1) 127(41.95,-4.1) 128(42.25,4.1) 129(42.55,-4.1) 130(42.85,4.1) 131(43.15,-4.1) 132(43.45,4.1) 133(43.75,-4.1) 134(44.05,4.1) 135(44.35,-4.1) 136(44.65,4.1) 137(44.95,-4.1) 138(45.25,4.1) 139(45.55,-4.1) 140(45.85,4.1) 141(46.15,-4.1) 142(46.45,4.1) 143(46.75,-4.1) 144(47.05,4.1) 145(47.35,-4.1) 146(47.65,4.1) 147(47.95,-4.1) 148(48.25,4.1) 149(48.55,-4.1) 150(48.85,4.1) 151(49.15,-4.1) 152(49.45,4.1) 153(49.75,-4.1) 154(50.05,4.1) 155(50.35,-4.1) 156(50.65,4.1) 157(50.95,-4.1) 158(51.25,4.1) 159(51.55,-4.1) 160(51.85,4.1) 161(52.15,-4.1) 162(52.45,4.1) 163(52.75,-4.1) 164(53.05,4.1) 165(53.35,-4.1) 166(53.65,4.1) 167(53.95,-4.1) 168(54.25,4.1) 169(54.55,-4.1) 170(54.85,4.1) 171(55.15,-4.1) 172(55.45,4.1) 173(55.75,-4.1) 174(56.05,4.1) 175(56.35,-4.1) 176(56.65,4.1) 177(56.95,-4.1) 178(57.25,4.1) 179(57.55,-4.1) 180(57.85,4.1) 181(58.15,-4.1) 182(58.45,4.1) 183(58.75,-4.1) 184(59.05,4.1) 185(59.35,-4.1) 186(59.65,4.1) 187(59.95,-4.1) 188(60.25,4.1) 189(60.55,-4.1) 190(60.85,4.1) 191(61.15,-4.1) 192(61.45,4.1) 193(61.75,-4.1) 194(62.05,4.1) 195(62.35,-4.1) 196(62.65,4.1) 197(62.95,-4.1) 198(63.25,4.1) 199(63.55,-4.1) 200(63.85,4.1) 201(64.15,-4.1) 202(64.45,4.1) 203(64.75,-4.1) 204(65.05,4.1)
  rect 3.556x4.699 smd: 205(0.6,12) 206(66.2,12)
